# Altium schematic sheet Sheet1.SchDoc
size A4
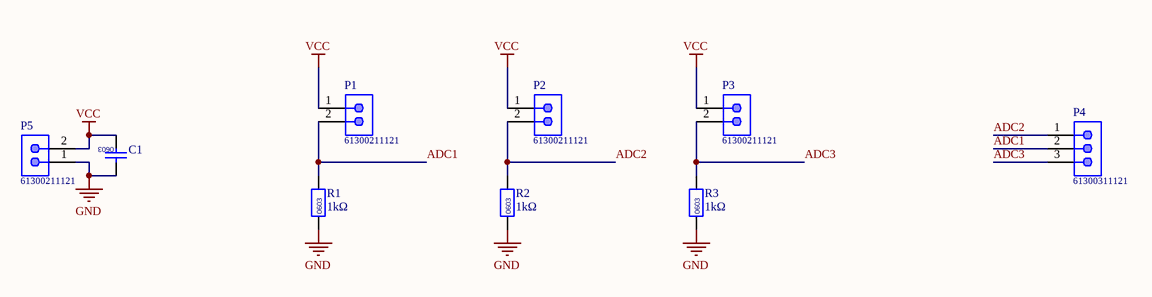
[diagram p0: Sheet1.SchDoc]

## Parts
C1  (no value)  [C_0603]
P1  61300211121  [61300211121]
P2  61300211121  [61300211121]
P3  61300211121  [61300211121]
P4  61300311121  [61300311121]
P5  61300211121  [61300211121]
R1  1kΩ  [R_0603]
R2  1kΩ  [R_0603]
R3  1kΩ  [R_0603]

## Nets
GND: C1.2 P5.1 R1.1 R2.1 R3.1
VCC: C1.1 P1.1 P2.1 P3.1 P5.2
ADC1: P1.2 P4.2 R1.2
ADC2: P2.2 P4.1 R2.2
ADC3: P3.2 P4.3 R3.2

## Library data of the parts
C1 = Capacitor_0603: MLCC - SMD/SMT Capacitor 50V
P1-P3 P5 = 61300211121: WR-PHD Pin Header, THT, pitch 2.54mm, Single Row, Vertical, 2p; Manufacturer: Wurth Elektronik; Pin Number: 2; Rated Current: 3A; Working Voltage: 250VAC; Withstanding Voltage: 500VAC; Contact Resistance: 20mOhm
P4 = 61300311121: WR-PHD Pin Header, THT, pitch 2.54mm, Single Row, Vertical, 3p; Manufacturer: Wurth Elektronik; Pin Number: 3; Rated Current: 3A; Working Voltage: 250VAC; Withstanding Voltage: 500VAC; Contact Resistance: 20mOhm
R1-R3 = Resistor_0603: SMT Resistor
